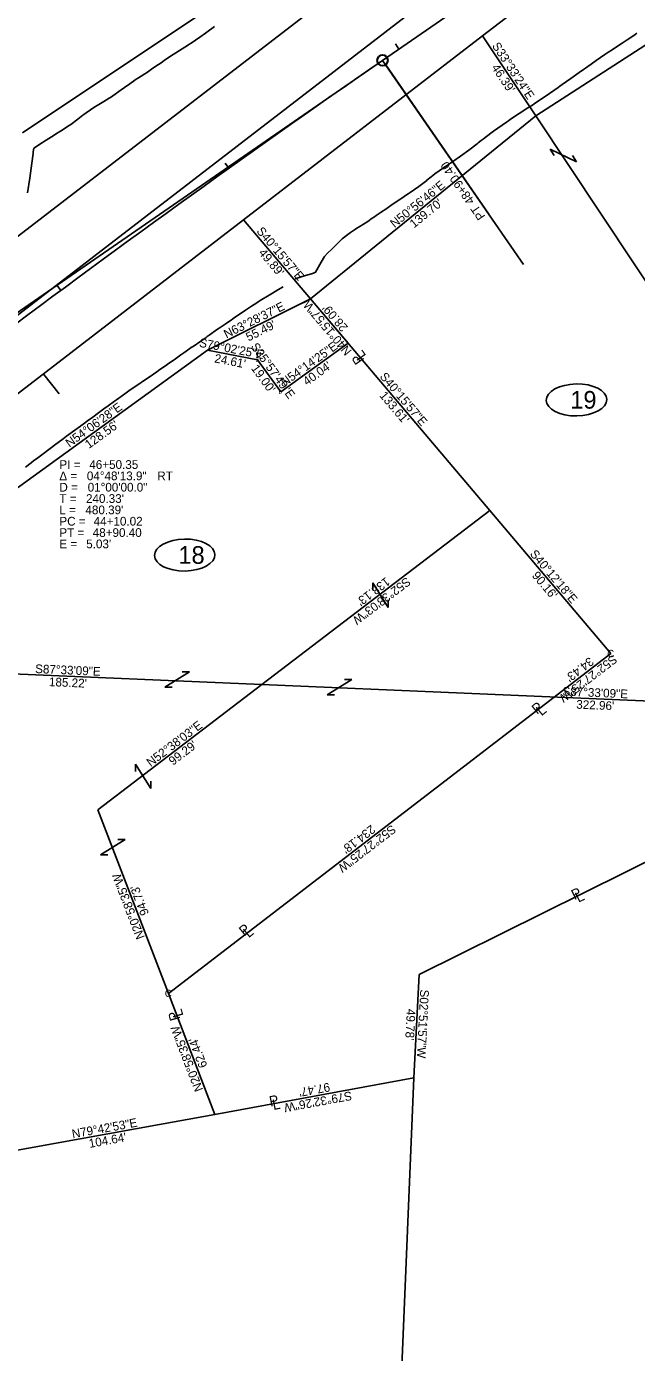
# Model space of a CAD drawing. Extents: x 1145508 to 2262867, y -3126236 to 2021677.
# Drawn here: x 1148038 to 1148331, y 2017346 to 2017985 of the extents above; entities that cross this region are included whole.
import ezdxf

# ---------------------------------------------------------------- set-up
doc = ezdxf.new("R2010")
doc.units = 0
for name, color, linetype in [('Default', 7, 'Continuous'), ('DSN_RDWY_Alignment', 7, 'Continuous'), ('DSN_RDWY_Alignment Annotation', 7, 'Continuous'), ('DSN_RDWY_Const Limits', 7, 'Continuous'), ('DSN_ROW_Annotation', 7, 'Continuous'), ('DSN_ROW_Esmnt', 7, 'Continuous'), ('DSN_ROW_Line', 7, 'Continuous'), ('DSN_ROW_Line-Annotation', 7, 'Continuous'), ('DSN_ROW_Prop-Line', 7, 'Continuous'), ('DSN_ROW_Prop-Line-Annotation', 7, 'Continuous'), ('E_Const Align', 7, 'Continuous'), ('EX_PRIMARY_CTL', 7, 'Continuous'), ('EX_QSECTION', 7, 'Continuous'), ('EX_ROW', 7, 'Continuous'), ('EX_ROW_ANNOT', 7, 'Continuous'), ('EX_SIGN', 7, 'Continuous')]:
    doc.layers.add(name, color=color, linetype=linetype)

msp = doc.modelspace()

# ---------------------------------------------------------------- linework, layer by layer
at = {"layer": 'Default'}
msp.add_line((1148336.03, 2018078.83), (1147725.18, 2017608.51), dxfattribs=at)
at = {"layer": 'DSN_RDWY_Alignment'}
msp.add_line((1148011.14, 2017831.73), (1148208.89, 2017968.31), dxfattribs=at)
msp.add_lwpolyline([(1148208.89, 2017968.31), (1148276.81, 2017869.96)], dxfattribs=at)
msp.add_circle((1148208.89, 2017968.31), 2.5, dxfattribs=at)
at = {"layer": 'DSN_RDWY_Alignment Annotation'}
for p, q in [((1148215.09, 2017976.23), (1148216.79, 2017973.76)), ((1148208.89, 2017968.31), (1148208.89, 2017968.31)), ((1148210.41, 2017966.11), (1148260.04, 2017894.25)), ((1148133.17, 2017918.79), (1148134.91, 2017916.35)), ((1148260.04, 2017894.25), (1148260.04, 2017894.25)), ((1148011.14, 2017831.73), (1148070.38, 2017872.65)), ((1148052.26, 2017859.94), (1148054.05, 2017857.52))]:
    msp.add_line(p, q, dxfattribs=at)
msp.add_circle((1148208.89, 2017968.31), 2.67, dxfattribs=at)
at = {"layer": 'DSN_RDWY_Const Limits'}
for points in [[(1148038.06, 2017904.51), (1148039.06, 2017911.56), (1148039.07, 2017911.65), (1148040.04, 2017918.85), (1148040.66, 2017923.46), (1148040.78, 2017924.26), (1148041.07, 2017925.99), (1148045.28, 2017928.79), (1148045.65, 2017929.04), (1148049.53, 2017931.54), (1148052.24, 2017933.23), (1148052.78, 2017933.56), (1148053.84, 2017934.22), (1148058.13, 2017936.91), (1148058.89, 2017937.48), (1148062.17, 2017939.95), (1148064.71, 2017941.86), (1148065.19, 2017942.22), (1148066.21, 2017942.99), (1148070.35, 2017945.88), (1148071.59, 2017946.63), (1148074.68, 2017948.51), (1148077.28, 2017950.09), (1148077.33, 2017950.12), (1148077.98, 2017950.51), (1148079.01, 2017951.16), (1148083.12, 2017954.09), (1148084.69, 2017955.24), (1148087.2, 2017957.07), (1148089.69, 2017958.82), (1148090.38, 2017959.25), (1148091.4, 2017959.89), (1148095.69, 2017962.58), (1148097.69, 2017964), (1148099.83, 2017965.48), (1148102.31, 2017967.19), (1148102.98, 2017967.65), (1148103.99, 2017968.34), (1148108.17, 2017971.18), (1148110.67, 2017972.75), (1148112.46, 2017973.87), (1148114.97, 2017975.43), (1148115.7, 2017975.91), (1148116.71, 2017976.6), (1148120.88, 2017979.46), (1148123.72, 2017981.43), (1148125.04, 2017982.34), (1148127.34, 2017984.11), (1148128.04, 2017984.66)], [(1148166.87, 2017863.1), (1148169.26, 2017863.87), (1148171.77, 2017864.75), (1148174.78, 2017865.59), (1148175.6, 2017865.82), (1148176.71, 2017866.33), (1148179.35, 2017871.15), (1148180.91, 2017873.94), (1148182.37, 2017875.44), (1148184.56, 2017877.34), (1148185.16, 2017877.98), (1148185.99, 2017878.88), (1148189.53, 2017882.45), (1148192.24, 2017884.47), (1148193.5, 2017885.41), (1148195.84, 2017887.03), (1148196.57, 2017887.5), (1148197.61, 2017888.15), (1148201.8, 2017890.8), (1148203.94, 2017892.26), (1148205, 2017892.99), (1148205.89, 2017893.59), (1148208.21, 2017895.18), (1148208.94, 2017895.68), (1148209.97, 2017896.38), (1148214.05, 2017899.19), (1148217.66, 2017901.64), (1148218.14, 2017901.97), (1148220.43, 2017903.51), (1148221.2, 2017904.03), (1148222.25, 2017904.73), (1148226.33, 2017907.53), (1148230.15, 2017910.53), (1148230.23, 2017910.59), (1148232.31, 2017912.31), (1148233.07, 2017912.94), (1148234.06, 2017913.75), (1148238.18, 2017916.49), (1148238.95, 2017916.99), (1148239.01, 2017917.03), (1148242.29, 2017919.25), (1148242.62, 2017919.47), (1148244.4, 2017920.72), (1148245.37, 2017921.41), (1148246.38, 2017922.12), (1148250.44, 2017925.04), (1148254.4, 2017928.1), (1148254.96, 2017928.53), (1148256.43, 2017929.67), (1148257.37, 2017930.39), (1148258.36, 2017931.16), (1148262.36, 2017934.17), (1148266.45, 2017937.05), (1148268.56, 2017938.54), (1148269.46, 2017939.17), (1148270.53, 2017939.93), (1148274.68, 2017942.73), (1148278.9, 2017945.41), (1148281.06, 2017946.81), (1148281.97, 2017947.41), (1148283.09, 2017948.15), (1148287.23, 2017950.95), (1148291.35, 2017953.78), (1148293.42, 2017955.25), (1148294.32, 2017955.89), (1148295.42, 2017956.68), (1148299.5, 2017959.58), (1148303.6, 2017962.44), (1148305.62, 2017963.85), (1148306.62, 2017964.56), (1148307.69, 2017965.32), (1148309.32, 2017966.48), (1148311.76, 2017968.23), (1148315.88, 2017971.06), (1148317.9, 2017972.42), (1148318.92, 2017973.1), (1148320.04, 2017973.83), (1148324.22, 2017976.58), (1148326.63, 2017978.17), (1148328.41, 2017979.35), (1148330.53, 2017980.77), (1148331.39, 2017981.35)], [(1148037, 2017772.45), (1148039.72, 2017774.48), (1148039.89, 2017774.61), (1148040.96, 2017775.42), (1148042.9, 2017776.89), (1148044.91, 2017778.4), (1148048.87, 2017781.37), (1148051.6, 2017783.45), (1148051.7, 2017783.54), (1148052.8, 2017784.38), (1148055.16, 2017786.11), (1148056.79, 2017787.31), (1148060.79, 2017790.22), (1148063.54, 2017792.22), (1148063.7, 2017792.33), (1148064.81, 2017793.11), (1148067.56, 2017795.14), (1148068.79, 2017796.05), (1148072.77, 2017798.99), (1148075.44, 2017800.95), (1148075.73, 2017801.16), (1148076.76, 2017801.92), (1148079.92, 2017804.23), (1148080.76, 2017804.84), (1148084.77, 2017807.74), (1148087.48, 2017809.61), (1148087.78, 2017809.81), (1148088.85, 2017810.55), (1148092.48, 2017813.04), (1148092.93, 2017813.35), (1148097.02, 2017816.15), (1148099.71, 2017817.98), (1148100.04, 2017818.23), (1148101.09, 2017818.96), (1148105.11, 2017821.76), (1148105.16, 2017821.79), (1148109.21, 2017824.63), (1148111.8, 2017826.45), (1148112.25, 2017826.77), (1148113.26, 2017827.48), (1148117.31, 2017830.32), (1148117.67, 2017830.56), (1148121.37, 2017833.15), (1148123.93, 2017834.93), (1148124.43, 2017835.28), (1148125.43, 2017835.98), (1148129.49, 2017838.8), (1148130.25, 2017839.33), (1148133.56, 2017841.63), (1148136.13, 2017843.39), (1148136.62, 2017843.72), (1148137.65, 2017844.42), (1148141.75, 2017847.18), (1148142.93, 2017847.98), (1148145.86, 2017849.95), (1148148.32, 2017851.6), (1148148.37, 2017851.63), (1148148.98, 2017852.05), (1148150.02, 2017852.64), (1148154.28, 2017855.19), (1148155.91, 2017856.19), (1148158.51, 2017857.77), (1148161.06, 2017859.33)]]:
    msp.add_lwpolyline(points, dxfattribs=at)
at = {"layer": 'DSN_ROW_Esmnt'}
for p, q in [((1148192.41, 2017832.07), (1148174.25, 2017853.51)), ((1148159.92, 2017808.67), (1148192.41, 2017832.07)), ((1148124.6, 2017828.73), (1148148.76, 2017824.05)), ((1148148.76, 2017824.05), (1148159.92, 2017808.67))]:
    msp.add_line(p, q, dxfattribs=at)
at = {"layer": 'DSN_ROW_Line'}
for p, q in [((1148035.64, 2017933.4), (1148226.66, 2018061.49)), ((1148282.74, 2017941.53), (1148421.63, 2018031.39)), ((1148174.25, 2017853.51), (1148282.74, 2017941.53)), ((1148124.6, 2017828.73), (1148174.25, 2017853.51)), ((1148020.45, 2017753.36), (1148124.6, 2017828.73))]:
    msp.add_line(p, q, dxfattribs=at)
at = {"layer": 'DSN_ROW_Line-Annotation'}
for centre in [(1148302.27, 2017804.81), (1148113.71, 2017730.11)]:
    msp.add_ellipse(centre, major_axis=(14.54, 0.23), ratio=0.529773, dxfattribs=at)
at = {"layer": 'DSN_ROW_Prop-Line'}
for p, q in [((1148257.09, 2017980.19), (1148282.74, 2017941.53)), ((1148282.74, 2017941.53), (1148473.5, 2017653.93)), ((1148142.01, 2017891.58), (1148174.25, 2017853.51)), ((1148174.25, 2017853.51), (1148260.61, 2017751.55)), ((1148260.61, 2017751.55), (1148150.83, 2017667.72)), ((1148260.61, 2017751.55), (1148318.81, 2017682.69)), ((1148318.81, 2017682.69), (1148291.51, 2017661.71)), ((1148071.92, 2017607.47), (1148150.83, 2017667.72)), ((1148291.51, 2017661.71), (1148105.83, 2017519.01)), ((1148475.13, 2017651.47), (1148226.52, 2017528.12)), ((1148105.83, 2017519.01), (1148071.92, 2017607.47)), ((1148226.52, 2017528.12), (1148224.03, 2017478.41)), ((1148128.19, 2017460.72), (1148105.83, 2017519.01)), ((1148224.03, 2017478.41), (1148128.19, 2017460.72)), ((1148208.6, 2017108), (1148224.03, 2017478.41)), ((1148025.23, 2017442.03), (1148128.19, 2017460.72))]:
    msp.add_line(p, q, dxfattribs=at)
at = {"layer": 'DSN_ROW_Prop-Line-Annotation'}
for p, q in [((1148291.58, 2017922.51), (1148289.66, 2017925.49)), ((1148289.66, 2017925.49), (1148302.29, 2017919.53)), ((1148302.29, 2017919.53), (1148300.37, 2017922.51)), ((1148211.68, 2017704.91), (1148204.29, 2017716.77)), ((1148204.29, 2017716.77), (1148204.29, 2017713.22)), ((1148211.68, 2017708.46), (1148211.68, 2017704.91)), ((1148104.11, 2017666.51), (1148115.97, 2017673.89)), ((1148115.97, 2017673.89), (1148112.42, 2017673.89)), ((1148107.66, 2017666.51), (1148104.11, 2017666.51)), ((1148182.24, 2017662.84), (1148194.1, 2017670.22)), ((1148194.1, 2017670.22), (1148190.55, 2017670.22)), ((1148185.79, 2017662.84), (1148182.24, 2017662.84)), ((1148097.33, 2017617.61), (1148089.95, 2017629.47)), ((1148089.95, 2017629.47), (1148089.95, 2017625.92)), ((1148097.33, 2017621.16), (1148097.33, 2017617.61)), ((1148085.02, 2017593.13), (1148073.16, 2017585.75)), ((1148081.47, 2017593.13), (1148085.02, 2017593.13)), ((1148073.16, 2017585.75), (1148076.71, 2017585.75))]:
    msp.add_line(p, q, dxfattribs=at)
at = {"layer": 'E_Const Align'}
msp.add_line((1148208.89, 2017968.31), (1148293.22, 2018026.54), dxfattribs=at)
msp.add_arc((1151464.82, 2013253.76), 5729.58, 124.62946, 129.43332, dxfattribs=at)
msp.add_arc((1151464.82, 2013253.76), 5729.58, 124.62946, 129.43332, dxfattribs=at)
at = {"layer": 'EX_QSECTION'}
for p, q in [((1147965.78, 2017675.63), (1148150.83, 2017667.72)), ((1148150.83, 2017667.72), (1148473.5, 2017653.93))]:
    msp.add_line(p, q, dxfattribs=at)
at = {"layer": 'EX_ROW'}
for p, q in [((1148354.33, 2018055.06), (1148257.09, 2017980.19)), ((1147970.9, 2017835.56), (1148239.28, 2018042.2)), ((1148257.09, 2017980.19), (1148142.01, 2017891.58)), ((1148142.01, 2017891.58), (1147948.7, 2017742.75))]:
    msp.add_line(p, q, dxfattribs=at)
at = {"layer": 'EX_SIGN'}
msp.add_line((1148045.87, 2017817.12), (1148053.16, 2017807.69), dxfattribs=at)

# ---------------------------------------------------------------- texts
at = {"layer": 'DSN_RDWY_Alignment Annotation'}
for s, p in [('48+90.40', (1148253.41, 2017900.68)), ('PT', (1148258.56, 2017893.23))]:
    msp.add_text(s, height=4.2, rotation=124.62946, dxfattribs=at).set_placement(p)
for s, p in [('PI = ', (1148053.34, 2017771.59)), ('46+50.35', (1148067.74, 2017771.59)), ('Δ = ', (1148053.34, 2017766.13)), ('04°48\'13.9"', (1148066.57, 2017766.13)), (' RT', (1148098.93, 2017766.13)), ('D = ', (1148053.34, 2017760.67)), ('01°00\'00.0"', (1148066.97, 2017760.67)), ('T = ', (1148053.34, 2017755.21)), ('L = ', (1148053.34, 2017749.75)), ("480.39'", (1148065.87, 2017749.75)), ("240.33'", (1148066.15, 2017755.21)), ('PC = ', (1148053.34, 2017744.29)), ('44+10.02', (1148069.84, 2017744.29)), ('PT = ', (1148053.34, 2017738.83)), ('48+90.40', (1148069.39, 2017738.83)), ('E = ', (1148053.34, 2017733.37)), ("5.03'", (1148066.26, 2017733.37))]:
    msp.add_text(s, height=4.2, dxfattribs=at).set_placement(p)
at = {"layer": 'DSN_ROW_Annotation'}
for s, rotation, p in [('S33°33\'24"E', 303.55678, (1148261.4, 2017975.32)), ("46.39'", 303.55678, (1148261.16, 2017964.83)), ('N50°56\'46"E', 39.05388, (1148214.68, 2017887.47)), ("139.70'", 39.05388, (1148224.05, 2017887.35)), ('S40°15\'57"E', 310.26597, (1148147.98, 2017885.92)), ("49.89'", 310.26597, (1148148.97, 2017875.47)), ('N63°28\'37"E', 26.52296, (1148133.76, 2017834.31)), ('N40°15\'57"W', 130.26597, (1148194.32, 2017828.42)), ("28.09'", 130.26597, (1148192.49, 2017839.87)), ("55.49'", 26.52296, (1148144.41, 2017832.91)), ('S79°02\'25"E', 349.04027, (1148120.39, 2017830.46)), ('S35°57\'49"E', 305.96348, (1148145.22, 2017830.45)), ('N54°14\'25"E', 35.75964, (1148161.8, 2017811.13)), ("24.61'", 349.04027, (1148127.71, 2017822.93)), ("19.00'", 305.96348, (1148145.42, 2017819.96)), ("40.04'", 35.75964, (1148172.53, 2017811.47)), ('S40°15\'57"E', 310.26597, (1148207.28, 2017815.9)), ("133.61'", 310.26597, (1148207.17, 2017806.76)), ('N54°06\'28"E', 35.89216, (1148058.18, 2017781.77)), ("128.56'", 35.89216, (1148067.53, 2017781.13)), ('S40°12\'18"E', 310.20507, (1148279.58, 2017730.51)), ("90.16'", 310.20507, (1148280.55, 2017720.06)), ('S52°38\'03"W', 217.36583, (1148220.39, 2017719.71)), ("138.13'", 217.36583, (1148210.46, 2017719.68)), ('S52°27\'25"W', 217.54319, (1148319.8, 2017682.32)), ("34.43'", 217.54319, (1148308.52, 2017681.21)), ('N52°38\'03"E', 37.36583, (1148097.28, 2017627.96)), ("99.29'", 37.36583, (1148107.99, 2017628.6)), ('S52°27\'25"W', 217.54319, (1148213.31, 2017600.48)), ("234.18'", 217.54319, (1148203.38, 2017600.41)), ('N20°58\'35"W', 110.97651, (1148094.5, 2017546.05)), ("94.73'", 110.97651, (1148096.56, 2017557.46)), ('S02°51\'57"W', 267.13414, (1148227.06, 2017520.97)), ("49.78'", 267.13414, (1148220.59, 2017511.66)), ('N20°58\'35"W', 110.97651, (1148122.64, 2017472.68)), ("62.44'", 110.97651, (1148124.69, 2017484.08)), ("97.47'", 190.4594, (1148183.2, 2017476.06)), ('S79°32\'26"W', 190.4594, (1148193.75, 2017471.9)), ('N79°42\'53"E', 10.28529, (1148059.76, 2017449.21)), ("104.64'", 10.28529, (1148067.92, 2017444.6))]:
    msp.add_text(s, height=4.2, rotation=rotation, dxfattribs=at).set_placement(p)
at = {"layer": 'DSN_ROW_Esmnt'}
for p in [(1148147.76, 2017823.05), (1148158.92, 2017807.67)]:
    msp.add_text('b', height=2, dxfattribs=at).set_placement(p)
at = {"layer": 'DSN_ROW_Line-Annotation'}
for s, p in [('19', (1148299.27, 2017800.6)), ('18', (1148110.63, 2017725.9))]:
    msp.add_text(s, height=8.5, dxfattribs=at).set_placement(p)
at = {"layer": 'DSN_ROW_Prop-Line-Annotation'}
for s, rotation, p in [('P', 125.89343, (1148200.33, 2017824.12)), ('L', 125.89343, (1148201.2, 2017826.18)), ('P', 39.23611, (1148283.27, 2017653.13)), ('L', 39.23611, (1148285.39, 2017652.39)), ('P', 26.04858, (1148301.29, 2017563.85)), ('L', 26.04858, (1148303.18, 2017562.63)), ('P', 39.23611, (1148142.33, 2017546.28)), ('L', 39.23611, (1148144.45, 2017545.53)), ('L', 106.2451, (1148113.12, 2017508.34)), ('P', 106.2451, (1148111.6, 2017506.68)), ('P', 11.11771, (1148154.89, 2017464.48)), ('L', 11.11771, (1148156.4, 2017462.82))]:
    msp.add_text(s, height=5, rotation=rotation, dxfattribs=at).set_placement(p)
at = {"layer": 'EX_PRIMARY_CTL'}
for p in [(1148317.06, 2017680.94), (1148104.08, 2017517.26)]:
    msp.add_text('C', height=3.5, dxfattribs=at).set_placement(p)
at = {"layer": 'EX_ROW_ANNOT'}
for s, p in [('S87°33\'09"E', (1148041.6, 2017673.29)), ('S87°33\'09"E', (1148041.6, 2017673.29)), ("185.22'", (1148048.24, 2017667.01)), ("185.22'", (1148048.24, 2017667.01)), ('S87°33\'09"E', (1148295.46, 2017662.44)), ('S87°33\'09"E', (1148295.46, 2017662.44)), ("322.96'", (1148302.1, 2017656.15)), ("322.96'", (1148302.1, 2017656.15))]:
    msp.add_text(s, height=4.2, rotation=357.55261, dxfattribs=at).set_placement(p)

doc.saveas('drawing.dxf')
